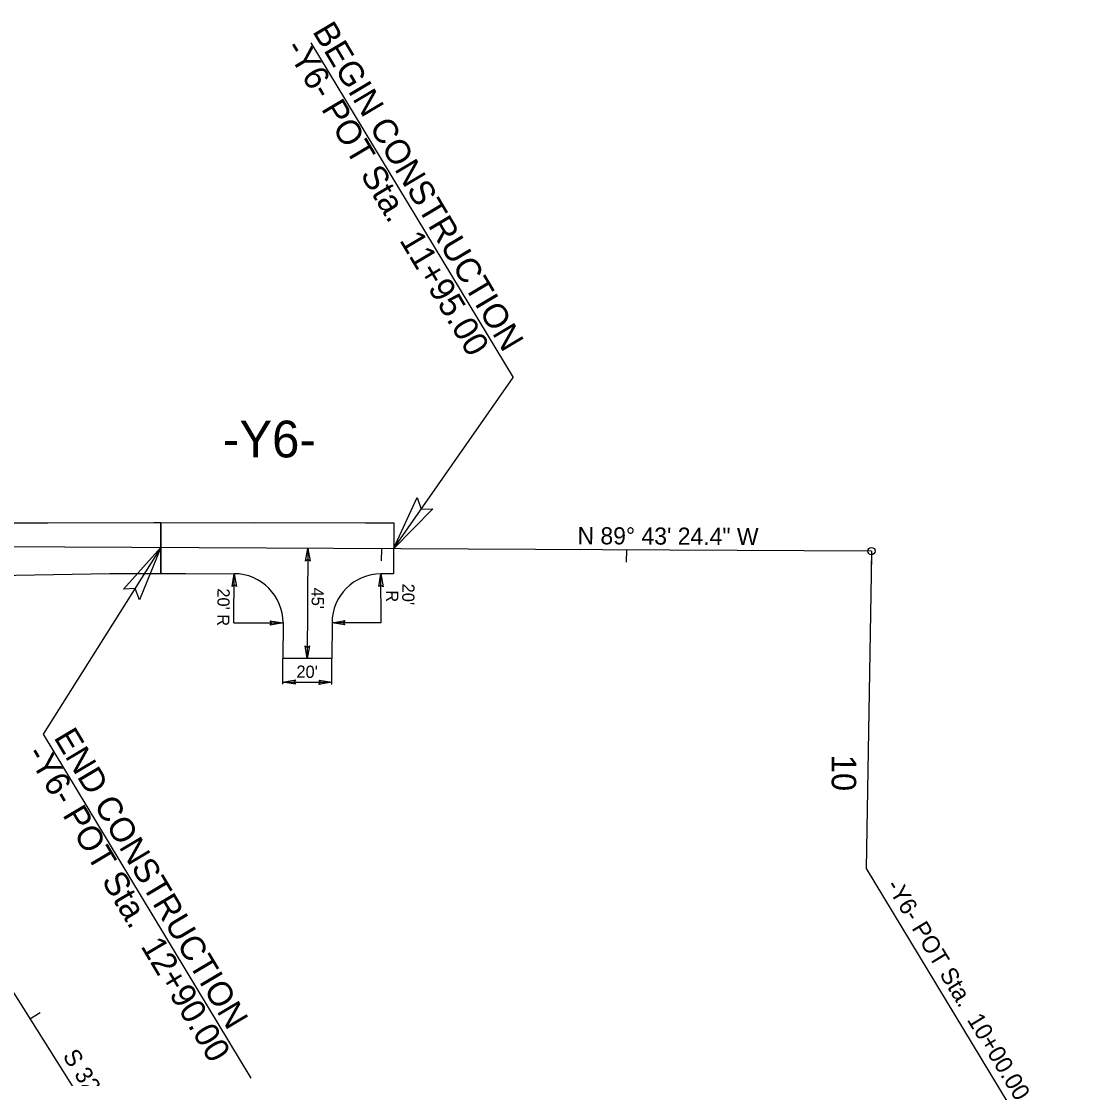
# Model space of a CAD drawing. Extents: x 1778969 to 1790720, y 807089 to 817794.
# Drawn here: x 1780645.9 to 1781076.4, y 815492.9 to 815924.7 of the extents above; entities that cross this region are included whole.
import ezdxf

# ---------------------------------------------------------------- set-up
doc = ezdxf.new("R2010")
doc.units = 0
for name, color, linetype in [('Prop Dimension', 7, 'Continuous'), ('Prop Dimension Text', 7, 'Continuous'), ('Prop EOT', 7, 'Continuous'), ('Prop Horizontal Alignment', 7, 'Continuous'), ('Prop Horizontal Alignment Direction Label', 7, 'Continuous'), ('Prop Horizontal Alignment Station Label', 7, 'Continuous'), ('Prop Horizontal Alignment Tick Label', 7, 'Continuous'), ('Prop Horizontal Alignment Tick Large', 7, 'Continuous'), ('Prop Horizontal Alignment Tick Small', 7, 'Continuous'), ('Prop Rem of Exist Asph Pvmt', 7, 'Continuous'), ('Prop Terminator CELL', 7, 'Continuous')]:
    doc.layers.add(name, color=color, linetype=linetype)

msp = doc.modelspace()

# ---------------------------------------------------------------- linework, layer by layer
at = {"layer": 'Prop Dimension'}
for p, q in [((1780762.95, 815709.44), (1780762.73, 815664.44)), ((1780732.81, 815679.09), (1780732.93, 815699.09)), ((1780792.81, 815678.98), (1780792.79, 815698.98)), ((1780732.81, 815679.09), (1780752.81, 815678.99)), ((1780792.81, 815678.98), (1780772.81, 815679.07)), ((1780752.69, 815653.94), (1780752.74, 815664.49)), ((1780772.69, 815653.84), (1780772.74, 815664.4)), ((1780752.69, 815654.86), (1780772.69, 815654.77))]:
    msp.add_line(p, q, dxfattribs=at)
at = {"layer": 'Prop EOT'}
for p, q in [((1780703.01, 815719.84), (1780702.91, 815699.18)), ((1780703.01, 815719.84), (1780741.31, 815719.99)), ((1780741.31, 815719.99), (1780786.5, 815719.84)), ((1780786.5, 815719.84), (1780798.01, 815719.85)), ((1780798.01, 815719.85), (1780797.91, 815698.98)), ((1780702.91, 815699.18), (1780713, 815699.2)), ((1780713, 815699.2), (1780732.93, 815699.09)), ((1780797.91, 815698.98), (1780792.79, 815698.98)), ((1780752.81, 815678.99), (1780752.74, 815664.49)), ((1780772.81, 815679.07), (1780772.74, 815664.4)), ((1780772.74, 815664.4), (1780752.74, 815664.49))]:
    msp.add_line(p, q, dxfattribs=at)
for centre, start, end in [((1780732.81, 815679.09), 359.7234, 89.6675), ((1780792.81, 815678.98), 90.0588, 179.7234)]:
    msp.add_arc(centre, 20, start, end, dxfattribs=at)
at = {"layer": 'Prop Horizontal Alignment'}
for p, q in [((1780487.95, 815773.73), (1781812.35, 813671.96)), ((1780487.95, 815773.73), (1781812.35, 813671.96)), ((1780992.95, 815708.33), (1780527.74, 815710.58))]:
    msp.add_line(p, q, dxfattribs=at)
at = {"layer": 'Prop Horizontal Alignment Station Label'}
for p, q in [((1780764.19, 815915.88), (1780846.68, 815779.22)), ((1780797.96, 815709.27), (1780846.68, 815779.22)), ((1780702.96, 815709.73), (1780654.86, 815633.6)), ((1780992.95, 815706.83), (1780990.85, 815578.79)), ((1780654.86, 815633.6), (1780739.63, 815493.15)), ((1780990.85, 815578.79), (1781054.6, 815473.18))]:
    msp.add_line(p, q, dxfattribs=at)
msp.add_circle((1780992.95, 815708.33), 1.5, dxfattribs=at)
at = {"layer": 'Prop Horizontal Alignment Tick Large'}
msp.add_line((1780992.95, 815708.33), (1780992.92, 815700.33), dxfattribs=at)
at = {"layer": 'Prop Horizontal Alignment Tick Small'}
for p, q in [((1780792.96, 815709.3), (1780792.93, 815704.3)), ((1780892.96, 815708.82), (1780892.93, 815703.82)), ((1780649.52, 815517.32), (1780653.75, 815519.98))]:
    msp.add_line(p, q, dxfattribs=at)
at = {"layer": 'Prop Rem of Exist Asph Pvmt'}
msp.add_line((1780702.91, 815699.18), (1780703.01, 815719.84), dxfattribs=at)
for points in [[(1780703.01, 815719.84), (1780700.12, 815719.83), (1780656.8, 815719.78), (1780615.39, 815719.68), (1780584.94, 815720.01)], [(1780624.33, 815698.15), (1780643.74, 815698.45), (1780682.2, 815699.14), (1780702.91, 815699.18)]]:
    msp.add_lwpolyline(points, dxfattribs=at)
at = {"layer": 'Prop Terminator CELL'}
for points in [[(1780814, 815725.52), (1780797.96, 815709.27), (1780807.61, 815730.13), (1780809.25, 815725.48)], [(1780687.66, 815692.78), (1780702.96, 815709.73), (1780694.25, 815688.47), (1780692.41, 815693.04)], [(1780762.03, 815704.26), (1780762.95, 815709.44), (1780763.84, 815704.23), (1780762.92, 815704.89)], [(1780732.01, 815693.91), (1780732.93, 815699.09), (1780733.82, 815693.87), (1780732.9, 815694.54)], [(1780791.87, 815693.8), (1780792.79, 815698.98), (1780793.69, 815693.76), (1780792.77, 815694.42)], [(1780747.63, 815679.91), (1780752.81, 815678.99), (1780747.59, 815678.09), (1780748.26, 815679.01)], [(1780777.99, 815678.15), (1780772.81, 815679.07), (1780778.03, 815679.97), (1780777.36, 815679.05)], [(1780763.65, 815669.62), (1780762.73, 815664.44), (1780761.83, 815669.66), (1780762.75, 815668.99)], [(1780757.87, 815653.94), (1780752.69, 815654.86), (1780757.91, 815655.76), (1780757.24, 815654.84)], [(1780767.51, 815655.68), (1780772.69, 815654.77), (1780767.48, 815653.87), (1780768.14, 815654.79)]]:
    msp.add_lwpolyline(points, close=True, dxfattribs=at)

# ---------------------------------------------------------------- texts
at = {"layer": 'Prop Dimension Text'}
for s, rotation, p in [("20' R", 269.3057, (1780726.09, 815693.13)), ("45'", 271.0407, (1780764.39, 815693.36)), ('R', 269.3057, (1780794.92, 815692.33)), ("20'", 269.3057, (1780801.51, 815695.04)), ("20'", 359.1927, (1780758.25, 815656.63))]:
    msp.add_text(s, height=5, rotation=rotation, dxfattribs=at).set_placement(p)
at = {"layer": 'Prop Horizontal Alignment Direction Label'}
for s, rotation, p in [('N 89%%d 43\' 24.4" W', 359.7234, (1780872.98, 815711.12)), ('S 32%%d 13\' 00.0" E', 302.2167, (1780662.65, 815502.24))]:
    msp.add_text(s, height=7, rotation=rotation, dxfattribs=at).set_placement(p)
at = {"layer": 'Prop Horizontal Alignment Station Label'}
for s, height, rotation, p in [('BEGIN CONSTRUCTION', 10, 300.775, (1780764.63, 815920.49)), ('-Y6- POT Sta.  11+95.00', 10, 300.775, (1780753.37, 815913.78)), ('-Y6-', 15, 359.8058, (1780728.27, 815746.65)), ('END CONSTRUCTION', 10, 300.775, (1780659.04, 815632.24)), ('-Y6- POT Sta.  12+90.00', 10, 300.775, (1780647.78, 815625.54)), ('-Y6- POT Sta.  10+00.00', 7, 301.1326, (1780998.71, 815571.78))]:
    msp.add_text(s, height=height, rotation=rotation, dxfattribs=at).set_placement(p)
at = {"layer": 'Prop Horizontal Alignment Tick Label'}
msp.add_text('10', height=10, rotation=269.7234, dxfattribs=at).set_placement((1780976.79, 815625.21))

doc.saveas('drawing.dxf')
